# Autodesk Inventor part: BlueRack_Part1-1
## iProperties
Shininess: 64.0
Length Units: 11272
Angle Units: 11279
Time Units: 11290
Mass Units: 11286
Length Display Precision: 3
Angle Display Precision: 2
Compacted: True
Part Number: BlueRack_Part1-1
Document SubType Name: Modeling
Created: 2004-12
Designer: John Blackburn
Material: Steel, Mild
Manufacturer: Standard
Standards Organization: Custom
Density: 0.0
Volumn: 0.0
Area: 0.0
PropertySet Name: Model Information
Control State: 0
Master: False
Checked Out: False
Author: John Blackburn
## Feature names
1. Extrusion1
2. Extrusion3
3. Extrusion4
